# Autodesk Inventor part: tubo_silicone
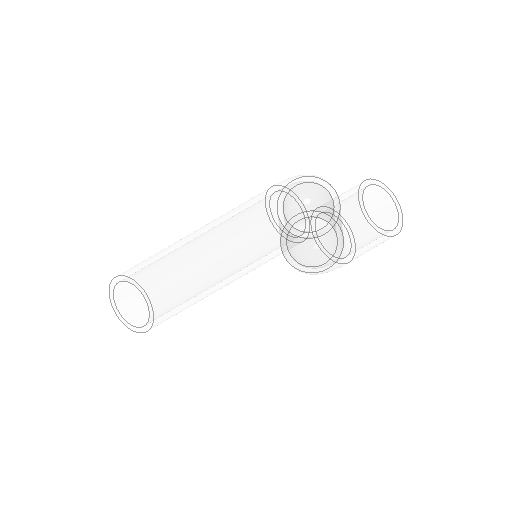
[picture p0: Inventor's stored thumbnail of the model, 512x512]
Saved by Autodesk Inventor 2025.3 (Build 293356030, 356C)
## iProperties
Created: 2026-03
Part Number: tubo_silicone
Material: Plastica PET
Document SubType Name: Modeling
Designer: Ryzen5700u
Density: 1.541 g/cm^3
Appearance: Policarbonato - Trasparente
Author: Ryzen5700u
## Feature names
1. Sweep1
## Parameters: d0 = 0.6 mm, d4 = 3.5 mm, d5 = 0.6 mm, d6 = 0, d7 = 0, d8 = 5 mm, d9 = 5 mm, d10 = 5 mm
